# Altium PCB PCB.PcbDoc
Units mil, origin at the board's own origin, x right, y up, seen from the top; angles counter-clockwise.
Board outline 4220 x 3450 mil, 2 copper layers (Top Layer, Bottom Layer), stack 62 mil thick; 138 components, 79 nets, 263 pads, 7 vias.
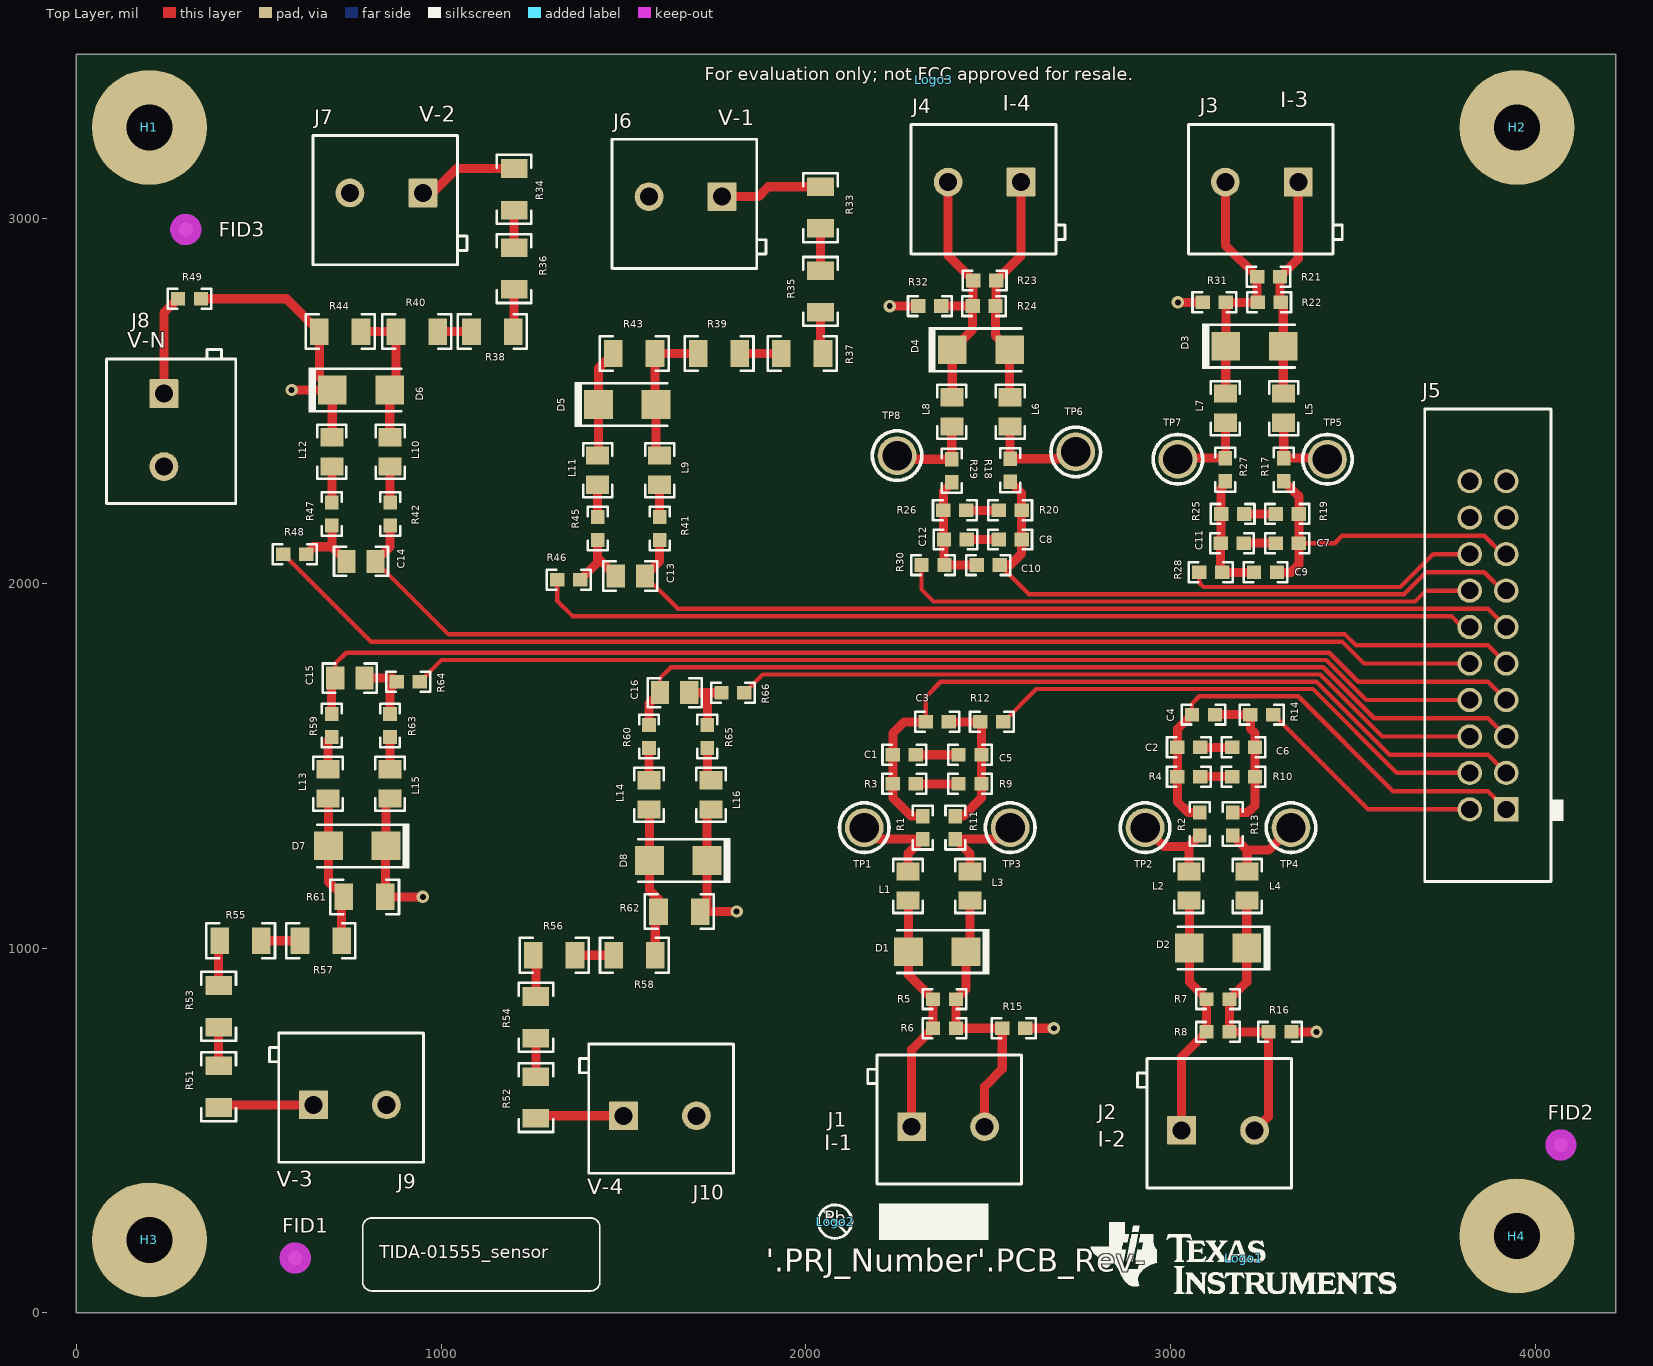
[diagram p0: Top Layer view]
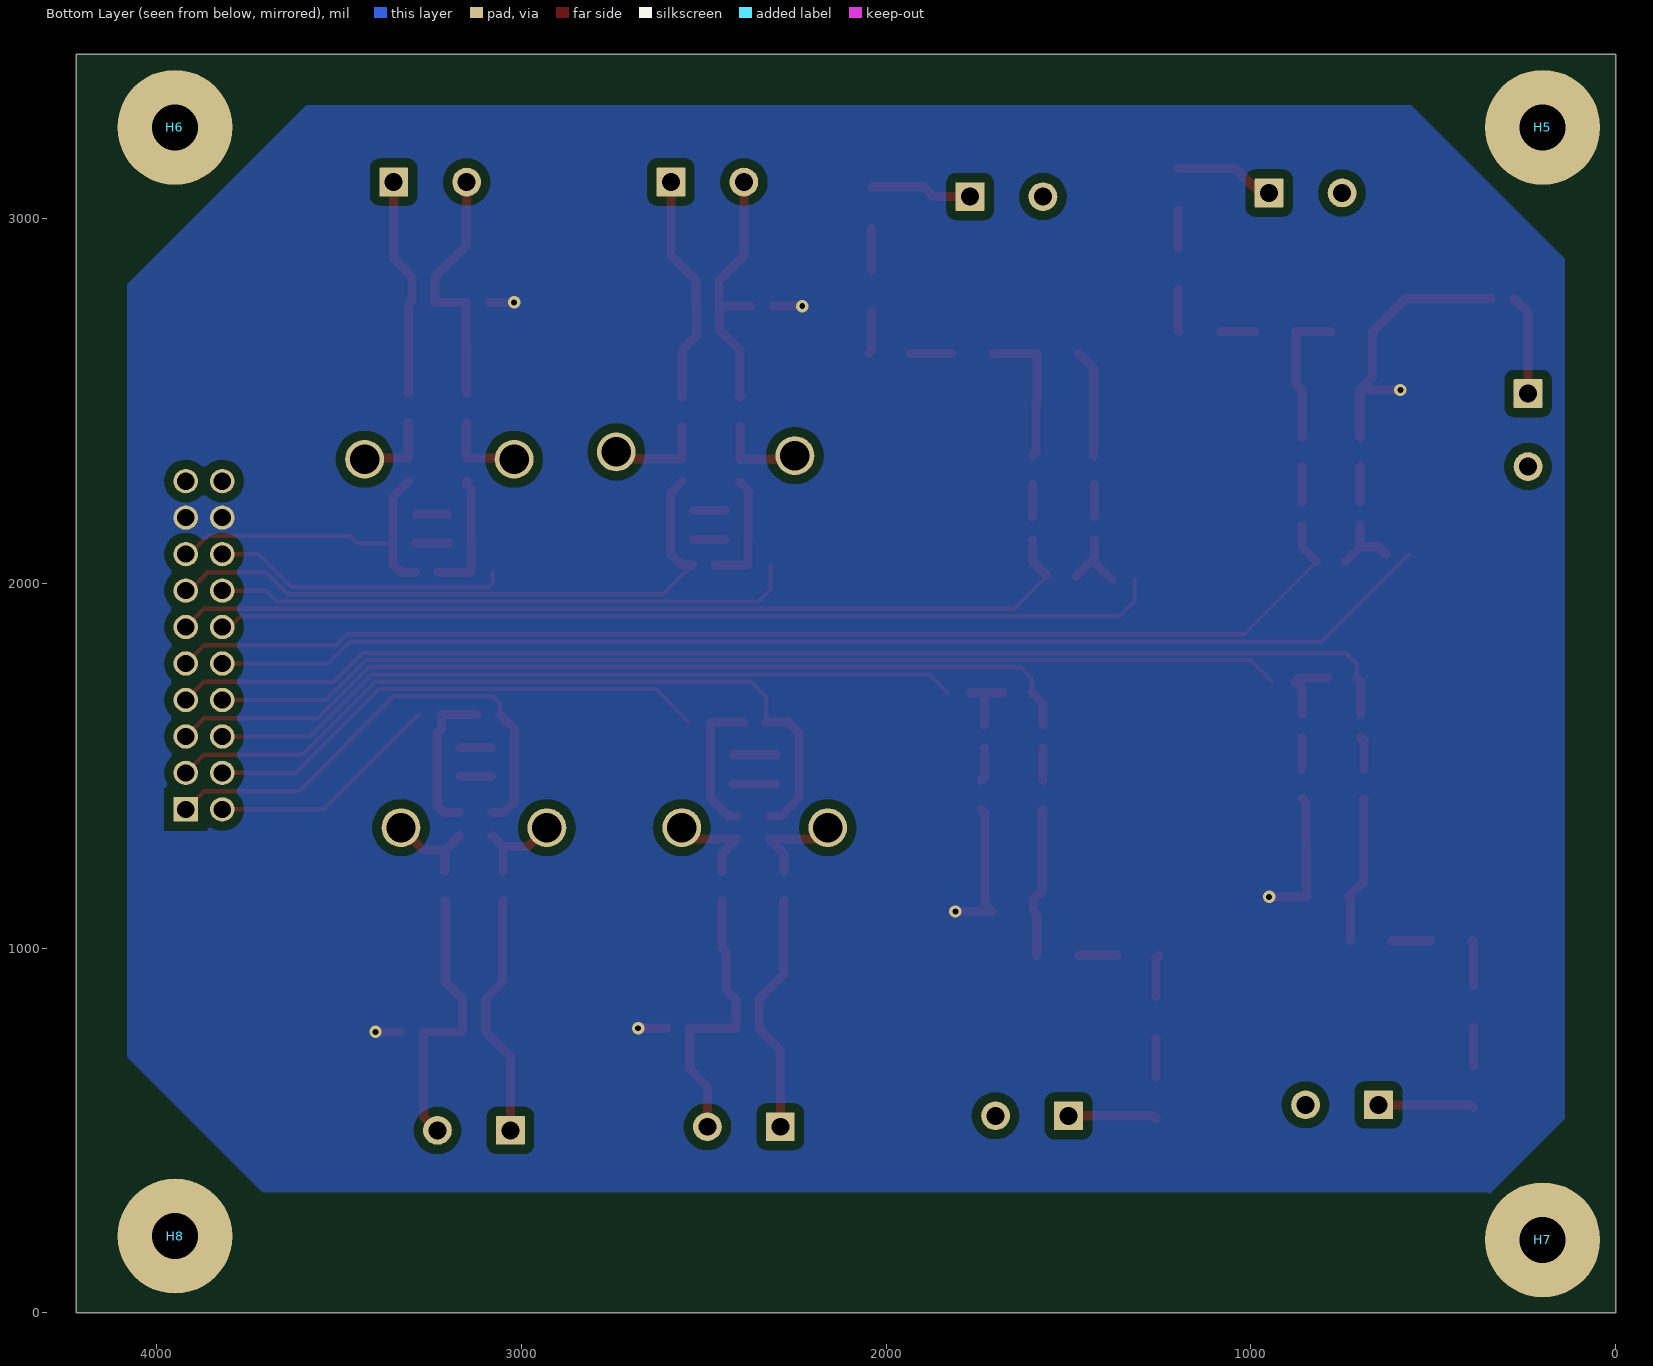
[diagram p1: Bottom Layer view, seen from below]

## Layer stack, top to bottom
Top Solder: solder mask 0.4, Solder Resist, Dk 3.5
Top Layer: signal copper 1.4
Dielectric1: core 59.2, FR-4, Dk 4.8
Bottom Layer: signal copper 1.4
Bottom Solder: solder mask 0.4, Solder Resist, Dk 3.5

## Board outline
0,0 4220,0 4220,3450 0,3450

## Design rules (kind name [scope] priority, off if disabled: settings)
AcuteAngle [All] p1: minimum=4.50000000000000E+0001 checktracksonly=FALSE
AssemblyTestPointUsage [All] p1: valid=2
BoardOutlineClearance BoardOutlineClearance_MountingHoles [OnCopper and InComponentClass('Mounting Holes')] p1: gap=40 ignorepadtopadclearanceinfootprint=FALSE
BoardOutlineClearance BoardOutlineClearance_Poly [OnCopper and IsPoly] p2: gap=25 ignorepadtopadclearanceinfootprint=FALSE
BoardOutlineClearance [OnCopper and Not InComponentClass('Logo') and not InComponentClass('FiducialMark') and not InRegion(1000,500,4000,800) and not InPoly] p3: gap=75 ignorepadtopadclearanceinfootprint=FALSE
Clearance Clearance_Keepouts [((IsTrack Or IsArc) And Not InPoly) And IsFree and IsKeepOut vs ((IsTrack Or IsArc) And Not InPoly) And IsFree and IsKeepOut] p1: gap=0 ignorepadtopadclearanceinfootprint=FALSE
Clearance Clearance_Poly [InPolygon] p2: gap=25 ignorepadtopadclearanceinfootprint=FALSE except(0: Arc-Hole Track-Hole SMDPad-Hole THPad-Hole Via-Hole Fill-Hole Poly-Hole Region-Hole Text-Hole)
Clearance [All] p3: gap=7.87 ignorepadtopadclearanceinfootprint=FALSE except(0: Arc-Hole Track-Hole SMDPad-Hole THPad-Hole Via-Hole Fill-Hole Poly-Hole Region-Hole Text-Hole)
ComponentClearance ComponentClearance_MountingHoles_FiducialMarks [InComponentClass('Mounting Holes') vs InComponentClass('FiducialMark')] p1: gap=50 collisioncheckmode=3 verticalgap=10 showdistances=FALSE
ComponentClearance ComponentClearance_Shunt [InComponentClass('Header') vs InComponentClass('Shunt')] p2: gap=0 collisioncheckmode=3 verticalgap=0 showdistances=FALSE
ComponentClearance ComponentClearance_Logo [InComponentClass('Logo')] p3: gap=50 collisioncheckmode=3 verticalgap=10 showdistances=FALSE
ComponentClearance ComponentClearance_ScrewToNut [(HasFootprint('NY PMS 440 0025 PH')) vs (HasFootprint('Keystone_1902C'))] p4: gap=5 collisioncheckmode=3 verticalgap=10 showdistances=FALSE
ComponentClearance ComponentClearance_MountingHoles [InComponentClass('Mounting Holes')] p5: gap=250 collisioncheckmode=3 verticalgap=100000 showdistances=FALSE
ComponentClearance ComponentClearance_SmallPassives [HasFootprint('0201*') or HasFootprint('0402*') or HasFootprint('0508') or HasFootprint('0603*') or HasFootprint('0612') or HasFootprint('0805*') or HasFootprint('0815*') or HasFootprint('0830*') or HasFootprint('1206*') or HasFootprint('1210*') or HasFootprint('1808*') or HasFootprint('1812*') or HasFootprint('1825*') or HasFootprint('2010*') or HasFootprint('2220*') or HasFootprint('2225*') or HasFootprint('2512*') or HasFootprint('2728*') or HasFootprint('3518*') vs HasFootprint('0201*') or HasFootprint('0402*') or HasFootprint('0508') or HasFootprint('0603*') or HasFootprint('0612') or HasFootprint('0805*') or HasFootprint('0815*') or HasFootprint('0830*') or HasFootprint('1206*') or HasFootprint('1210*') or HasFootprint('1808*') or HasFootprint('1812*') or HasFootprint('1825*') or HasFootprint('2010*') or HasFootprint('2220*') or HasFootprint('2225*') or HasFootprint('2512*') or HasFootprint('2728*') or HasFootprint('3518*')] p6: gap=14.96 collisioncheckmode=3 verticalgap=10 showdistances=FALSE
ComponentClearance ComponentClearance_THtoSMT [IsThruComponent vs IsSMTComponent] p7: gap=40 collisioncheckmode=3 verticalgap=30 showdistances=FALSE
ComponentClearance ComponentClearance_THtoTH [IsThruComponent vs IsThruComponent] p8: gap=30 collisioncheckmode=3 verticalgap=30 showdistances=FALSE
ComponentClearance [All] p9: gap=30 collisioncheckmode=3 verticalgap=10 showdistances=FALSE
DiffPairsRouting [All] p1: maxlimit=100 minlimit=10 mostfreqgap=10 toplayer_minwidth=15 toplayer_maxwidth=15 toplayer_prefwidth=15 bottomlayer_minwidth=15 bottomlayer_maxwidth=15 bottomlayer_prefwidth=15 maxuncoupledlength=1000
FabricationTestPointUsage TestPointUsage [All] p1: valid=2 allowmultiple=FALSE
FabricationTestpoint Testpoint [All] p1: side=3 testpointundercomponent=TRUE minsize=40 maxsize=100 preferedsize=60 minholesize=0 maxholesize=40 preferedholesize=32 testpointgrid=1 allowsidetop=TRUE allowsidebottom=TRUE usegrid=TRUE gridtolerance=0.01
FanoutControl Fanout_LCC [IsLCC] p1: bgadir=Out bgaviamode=Centered fanoutstyle=Auto fanoutdirection=Alternating viagrid=1 // Fanout_LCC (Default Rule)
FanoutControl Fanout_BGA [IsBGA] p2: bgadir=Out bgaviamode=Centered fanoutstyle=Auto fanoutdirection=Alternating viagrid=1 // Fanout_BGA (Default Rule)
FanoutControl Fanout_Default [All] p4: bgadir=Out bgaviamode=Centered fanoutstyle=Auto fanoutdirection=Alternating viagrid=1 // Fanout_Default (Default Rule)
FanoutControl Fanout_Small [(CompPinCount < 5)] p5: bgadir=Out bgaviamode=Centered fanoutstyle=Auto fanoutdirection=OutThenIn viagrid=1 // Fanout_Small (Default Rule)
HoleSize [All] p1: absolutevalues=TRUE maxlimit=251 minlimit=7.87 maxpercent=80.000 minpercent=20.000
MinimumAnnularRing MinimumAnnularRing_ThermalPadVias [IsVia and InAnyComponent] p1: minimumring=5.91
MinimumAnnularRing [All] p2: minimumring=8
MinimumSolderMaskSliver MinimumSolderMaskSliver_Logo [InComponentClass('Logo') vs InComponentClass('Logo')] p1: minsoldermaskwidth=0.7
MinimumSolderMaskSliver [All] p2: minsoldermaskwidth=3.94
PlaneConnect [All] p1: planeconnectstyle=Relief reliefexpansion=10 reliefentries=4 reliefconductorwidth=10 reliefairgap=10
PolygonConnect [All] p1: connectstyle=Direct reliefconductorwidth=10 reliefentries=4 polygonreliefangle="90 Angle" airgapwidth=10
RoutingVias ThermalPadVias [IsVia and InAnyComponent] p1: holewidth=7.87 width=19.68 viastyle="Through Hole" minholewidth=7.87 minwidth=19.68 maxholewidth=12.99 maxwidth=23.62
RoutingVias [All] p2: holewidth=16 width=34 viastyle="Through Hole" minholewidth=7.87 minwidth=26 maxholewidth=40 maxwidth=65
SilkToBoardRegionClearance [Not ((IsComment or IsDesignator) And (Hide <> 'False')) and not InRegion(1000,500,4000,800)] p1:
SilkToSilkClearance SilkToSilkClearance_Pb-FreeLogo [(HasFootprint('Pb-Free_Overlay_Medium') OR HasFootprint('Pb-Free_Overlay_Small')) vs (HasFootprint('Pb-Free_Overlay_Medium') OR HasFootprint('Pb-Free_Overlay_Small'))] p1: silktosilkclearance=0
SilkToSilkClearance [All] p2: silktosilkclearance=4
SilkToSolderMaskClearance SilkToComponentPadClearance [(IsPad or IsFill or IsRegion) and InAnycomponent] p1: minsilkscreentomaskgap=5 clearancetoexposedcopper=TRUE
SilkToSolderMaskClearance "Silk to Solder Mask Opening" [All] p2: minsilkscreentomaskgap=4 clearancetoexposedcopper=FALSE
SolderMaskExpansion [All] p1: expansion=1.97
Width [All] p1: maxlimit=100 minlimit=6 preferedwidth=10 checkconnectedcopper=TRUE
15 further rules are at their usual default settings.

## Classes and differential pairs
component class PT: C13 C14 C15 C16 D5 D6 D7 D8 J6 J7 J8 J9 J10 L9 L10 L11 L12 L13 L14 L15 L16 R33 R34 R35 R36 R37 R38 R39 R40 R41 R42 R43 R44 R45 R46 R47 R48 R49 R51 R52 R53 R54 R55 R56 R57 R58 R59 R60 R61 R62 R63 R64 R65 R66
component class CT: C1 C2 C3 C4 C5 C6 C7 C8 C9 C10 C11 C12 D1 D2 D3 D4 J1 J2 J3 J4 J5 L1 L2 L3 L4 L5 L6 L7 L8 R1 R2 R3 R4 R5 R6 R7 R8 R9 R10 R11 R12 R13 R14 R15 R16 R17 R18 R19 R20 R21 R22 R23 R24 R25 R26 R27 R28 R29 R30 R31 R32 TP1 TP2 TP3 TP4 TP5 TP6 TP7 TP8
component class "Mounting Holes": H1 H2 H3 H4
component class Logo: Logo1
component class EVM_Hardware: FID1 FID2 FID3 H1 H2 H3 H4 H5 H6 H7 H8 Logo1 Logo2 Logo3 TIDA-01555_sensor
component class FiducialMark: FID1 FID2 FID3
component class Label: TIDA-01555_sensor

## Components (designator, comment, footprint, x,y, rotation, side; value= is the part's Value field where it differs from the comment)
C1 "C0603X102K5RACTU" 0603 2270,1530 r0 top value=1000pF
C2 "C0603X102K5RACTU" 0603 3050,1550 r0 top value=1000pF
C3 "06031C103JAT2A" 0603 2360,1620 r0 top value=0.01uF
C4 "06031C103JAT2A" 0603 3090,1640 r0 top value=0.01uF
C5 "C0603X102K5RACTU" 0603 2450,1530 r0 top value=1000pF
C6 "C0603X102K5RACTU" 0603 3200,1550 r0 top value=1000pF
C7 "C0603X102K5RACTU" 0603 3320,2110 r180 top value=1000pF
C8 "C0603X102K5RACTU" 0603 2560,2120 r180 top value=1000pF
C9 "06031C103JAT2A" 0603 3260,2030 r180 top value=0.01uF
C10 "06031C103JAT2A" 0603 2500,2050 r180 top value=0.01uF
C11 "C0603X102K5RACTU" 0603 3168.5,2110 r180 top value=1000pF
C12 "C0603X102K5RACTU" 0603 2410,2120 r180 top value=1000pF
C13 "08055A331KAT2A" 0805_HV 1519.06,2020 r180 top value=330pF
C14 "08055A331KAT2A" 0805_HV 780.32,2060 r180 top value=330pF
C15 "08055A331KAT2A" 0805_HV 749.92,1740 r0 top value=330pF
C16 "08055A331KAT2A" 0805_HV 1640,1700 r0 top value=330pF
D1 "SMAJ12CA" SMA 2360,990 r180 top value=12V
D2 "SMAJ12CA" SMA 3130,1000 r180 top value=12V
D3 "SMAJ12CA" SMA 3230,2650 r0 top value=12V
D4 "SMAJ12CA" SMA 2480,2640 r0 top value=12V
D5 "SMAJ12CA" SMA 1510.31,2490 r0 top value=12V
D6 "SMAJ12CA" SMA 780.31,2530 r0 top value=12V
D7 "SMAJ12CA" SMA 769.92,1280 r180 top value=12V
D8 "SMAJ12CA" SMA 1650,1240 r180 top value=12V
FID1 "Fiducial" Fiducial10-20 600,150 r0 top
FID2 "Fiducial" Fiducial10-20 4070,460 r0 top
FID3 "Fiducial" Fiducial10-20 300,2970 r0 top
H1 "NY PMS 440 0025 PH" "NY PMS 440 0025 PH" 200,3250 r0 top locked
H2 "NY PMS 440 0025 PH" "NY PMS 440 0025 PH" 3950,3250 r0 top locked
H3 "NY PMS 440 0025 PH" "NY PMS 440 0025 PH" 200,200 r0 top locked
H4 "NY PMS 440 0025 PH" "NY PMS 440 0025 PH" 3949.47,210 r0 top locked
H5 "1902C" Keystone_1902C 200,3250 r180 bottom locked
H6 "1902C" Keystone_1902C 3950,3250 r180 bottom locked
H7 "1902C" Keystone_1902C 200,200 r180 bottom locked
H8 "1902C" Keystone_1902C 3949.47,210 r180 bottom locked
J1 "ED120/2DS" On-Shore_ED120_2DS 2390,510 r0 top
J2 "ED120/2DS" On-Shore_ED120_2DS 3130,500 r0 top
J3 "ED120/2DS" On-Shore_ED120_2DS 3250,3100 r180 top
J4 "ED120/2DS" On-Shore_ED120_2DS 2490,3100 r180 top
J5 "SBH11-PBPC-D10-ST-BK" Sullins_SBH11-xxxC-D10-ST 3870,1830 r180 top
J6 "ED120/2DS" On-Shore_ED120_2DS 1670,3060 r180 top
J7 "ED120/2DS" On-Shore_ED120_2DS 850,3070 r180 top
J8 "ED120/2DS" On-Shore_ED120_2DS 240,2420 r270 top
J9 "ED120/2DS" On-Shore_ED120_2DS 750,570 r0 top
J10 "ED120/2DS" On-Shore_ED120_2DS 1600,540 r0 top
L1 "FBMJ2125HM210NT" 0805_HV 2280,1170 r90 top value="21 ohm"
L2 "FBMJ2125HM210NT" 0805_HV 3050,1170 r90 top value="21 ohm"
L3 "FBMJ2125HM210NT" 0805_HV 2450,1170 r90 top value="21 ohm"
L4 "FBMJ2125HM210NT" 0805_HV 3210,1170 r90 top value="21 ohm"
L5 "FBMJ2125HM210NT" 0805_HV 3310,2480 r270 top value="21 ohm"
L6 "FBMJ2125HM210NT" 0805_HV 2560,2470 r270 top value="21 ohm"
L7 "FBMJ2125HM210NT" 0805_HV 3150,2480 r270 top value="21 ohm"
L8 "FBMJ2125HM210NT" 0805_HV 2400,2470 r270 top value="21 ohm"
L9 "FBMJ2125HM210NT" 0805_HV 1599.06,2310 r270 top value="21 ohm"
L10 "FBMJ2125HM210NT" 0805_HV 860.31,2360 r270 top value="21 ohm"
L11 "FBMJ2125HM210NT" 0805_HV 1429.06,2310 r270 top value="21 ohm"
L12 "FBMJ2125HM210NT" 0805_HV 700.31,2360 r270 top value="21 ohm"
L13 "FBMJ2125HM210NT" 0805_HV 689.92,1450 r90 top value="21 ohm"
L14 "FBMJ2125HM210NT" 0805_HV 1570,1420 r90 top value="21 ohm"
L15 "FBMJ2125HM210NT" 0805_HV 859.92,1450 r90 top value="21 ohm"
L16 "FBMJ2125HM210NT" 0805_HV 1740,1420 r90 top value="21 ohm"
Logo1 "Texas Instruments" TI_Stacked_Overlay_Small 3200,150 r0 top
Logo2 "Pb-Free Symbol" Pb-Free_Overlay_Small 2080,250 r0 top
Logo3 "FCC disclaimer" FCC_disclaimer 2350,3380 r0 top
R1 "CRCW06031K00JNEA" 0603 2320,1330 r270 top value=1.0k
R2 "CRCW06031K00JNEA" 0603 3080,1340 r270 top value=1.0k
R3 "RC0603FR-07100KL" 0603 2270,1450 r180 top value=100k
R4 "RC0603FR-07100KL" 0603 3050,1470 r180 top value=100k
R5 "CRCW0603200RFKEA" 0603 2380,860 r180 top value=200
R6 "CRCW0603200RFKEA" 0603 2380,780 r180 top value=200
R7 "CRCW0603200RFKEA" 0603 3130,860 r180 top value=200
R8 "CRCW0603200RFKEA" 0603 3130,770 r180 top value=200
R9 "RC0603FR-07100KL" 0603 2450,1450 r180 top value=100k
R10 "RC0603FR-07100KL" 0603 3200,1470 r180 top value=100k
R11 "CRCW06031K00JNEA" 0603 2410,1330 r270 top value=1.0k
R12 "CRCW06030000Z0EA" 0603 2510,1620 r0 top value=0
R13 "CRCW06031K00JNEA" 0603 3170,1340 r270 top value=1.0k
R14 "CRCW06030000Z0EA" 0603 3250,1640 r0 top value=0
R15 "CRCW06030000Z0EA" 0603 2570,780 r180 top value=0
R16 "CRCW06030000Z0EA" 0603 3300,770 r180 top value=0
R17 "CRCW06031K00JNEA" 0603 3310,2311.5 r90 top value=1.0k
R18 "CRCW06031K00JNEA" 0603 2560,2310 r90 top value=1.0k
R19 "RC0603FR-07100KL" 0603 3320,2190 r0 top value=100k
R20 "RC0603FR-07100KL" 0603 2560,2200 r0 top value=100k
R21 "CRCW0603200RFKEA" 0603 3268.5,2840 r0 top value=200
R22 "CRCW0603200RFKEA" 0603 3270,2770 r0 top value=200
R23 "CRCW0603200RFKEA" 0603 2490,2830 r0 top value=200
R24 "CRCW0603200RFKEA" 0603 2488.5,2760 r0 top value=200
R25 "RC0603FR-07100KL" 0603 3170,2190 r0 top value=100k
R26 "RC0603FR-07100KL" 0603 2408.5,2200 r0 top value=100k
R27 "CRCW06031K00JNEA" 0603 3150,2311.5 r90 top value=1.0k
R28 "CRCW06030000Z0EA" 0603 3110,2030 r180 top value=0
R29 "CRCW06031K00JNEA" 0603 2400,2308.5 r90 top value=1.0k
R30 "CRCW06030000Z0EA" 0603 2348.5,2050 r180 top value=0
R31 "CRCW06030000Z0EA" 0603 3120,2770 r0 top value=0
R32 "CRCW06030000Z0EA" 0603 2340,2760 r0 top value=0
R33 "RC1206FR-07330KL" 1206 2040,3030 r90 top value=330k
R34 "RC1206FR-07330KL" 1206 1200,3080 r90 top value=330k
R35 "RC1206FR-07330KL" 1206 2040,2800 r90 top value=330k
R36 "RC1206FR-07330KL" 1206 1200,2862.91 r90 top value=330k
R37 "RC1206FR-07330KL" 1206 1990,2630 r0 top value=330k
R38 "RC1206FR-07330KL" 1206 1140.31,2690 r0 top value=330k
R39 "RC1206FR-07330KL" 1206 1761.97,2630 r0 top value=330k
R40 "RC1206FR-07330KL" 1206 933.23,2690 r0 top value=330k
R41 "RC0603FR-0712RL" 0603 1599.06,2150 r270 top value=12.0
R42 "RC0603FR-0712RL" 0603 860.31,2190 r270 top value=12.0
R43 "CRCW120629K4FKEA" 1206 1529.06,2630 r180 top value=29.4k
R44 "CRCW120629K4FKEA" 1206 723.23,2690 r180 top value=29.4k
R45 "RC0603FR-0712RL" 0603 1429.06,2150 r270 top value=12.0
R46 "CRCW06030000Z0EA" 0603 1350,2010 r180 top value=0
R47 "RC0603FR-0712RL" 0603 700.31,2190 r270 top value=12.0
R48 "CRCW06030000Z0EA" 0603 598.82,2080 r180 top value=0
R49 "CRCW06030000Z0EA" 0603 310,2780 r180 top value=0
R51 "RC1206FR-07330KL" 1206 390,620 r270 top value=330k
R52 "RC1206FR-07330KL" 1206 1260,590 r270 top value=330k
R53 "RC1206FR-07330KL" 1206 390,840 r270 top value=330k
R54 "RC1206FR-07330KL" 1206 1260,810 r270 top value=330k
R55 "RC1206FR-07330KL" 1206 450,1020 r180 top value=330k
R56 "RC1206FR-07330KL" 1206 1310,980 r180 top value=330k
R57 "RC1206FR-07330KL" 1206 670,1020 r180 top value=330k
R58 "RC1206FR-07330KL" 1206 1530,980 r180 top value=330k
R59 "RC0603FR-0712RL" 0603 699.92,1610 r90 top value=12.0
R60 "RC0603FR-0712RL" 0603 1570,1580 r90 top value=12.0
R61 "CRCW120629K4FKEA" 1206 790,1140 r0 top value=29.4k
R62 "CRCW120629K4FKEA" 1206 1652.91,1100 r0 top value=29.4k
R63 "RC0603FR-0712RL" 0603 859.92,1610 r90 top value=12.0
R64 "CRCW06030000Z0EA" 0603 909.92,1730 r0 top value=0
R65 "RC0603FR-0712RL" 0603 1730,1580 r90 top value=12.0
R66 "CRCW06030000Z0EA" 0603 1800,1700 r0 top value=0
TIDA-01555_sensor "Size: 0.65\" x 0.20 \"" Label_650x200 1110,160 r0 top
TP1 "1573-2" Keystone1573-2 2160,1330 r0 top
TP2 "1573-2" Keystone1573-2 2930,1330 r0 top
TP3 "1573-2" Keystone1573-2 2560,1330 r0 top
TP4 "1573-2" Keystone1573-2 3330,1330 r0 top
TP5 "1573-2" Keystone1573-2 3430,2340 r0 top
TP6 "1573-2" Keystone1573-2 2740,2360 r0 top
TP7 "1573-2" Keystone1573-2 3020,2340 r0 top
TP8 "1573-2" Keystone1573-2 2250,2350 r0 top

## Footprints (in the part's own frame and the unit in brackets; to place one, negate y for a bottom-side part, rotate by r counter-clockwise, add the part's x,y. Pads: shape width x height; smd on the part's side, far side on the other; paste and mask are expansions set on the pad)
0603 [mm] "0603 from SM-752 data"
  rect 1x0.95 smd: 1(-0.8,0) 2(0.8,0)
  silkscreen extent -1.52,-0.69 1.52,0.69, body extent -0.87,-0.47 0.87,0.47, height 1
0805_HV [mil] "0805 with 30mil clearance between pads"
  rect 50x63 smd: 1(-40,0) 2(40,0)
  silkscreen extent -74,-40 74,40, body extent -43,-29 43,29, height 57
1206 [mm] "1206 from SM-752 data"
  rect 1.3x1.85 smd: 1(-1.45,0) 2(1.45,0)
  silkscreen extent -2.4,-1.21 2.4,1.21, body extent -1.7,-0.9 1.7,0.9, height 1.35
FCC_disclaimer [mil]
Fiducial10-20 [mm]
  round 1 smd mask+0.5: 1(0,0)
  Top Layer keep-out circle w1.178: c0,0 r0.5
Keystone1573-2 [mm] "Double Turret"
  round 2.7 hole 2.05: 1(0,0)
  silkscreen extent -1.73,-1.73 1.73,1.73, body extent -1.18,-1.18 1.17,1.18, height 4.72
Keystone_1902C [mil] "Hex Standoff, 4-40 threaded, nylon"
  body extent -145,-126 146,126, height 501
Label_650x200 [mil] "Thermal Transfer Label"
  silkscreen extent -325,-100 325,100, body extent -325,-100 325,100, height 1
"NY PMS 440 0025 PH" [mm] "4-40 nylon screw and mounting hole"
  round 8 hole 3.2: 1(0,0)
  body extent -3.3,-3.3 3.3,3.3, height 2.69
On-Shore_ED120_2DS [mm] "ONSHORE"
  rrect5% 2x2 hole 1.25: 1(-2.54,0)
  round 2 hole 1.25: 2(2.54,0)
  silkscreen extent -5.6,-4 5.12,5, body extent -5.78,-4 5.08,5, height 13
Pb-Free_Overlay_Small [mil]
  silkscreen extent -46,-46 46,46
SMA [mm] "Molded Diode, 2-Leads, Body 4.3x2.6mm, IPC Medium Density, based on OnSemi component dimensions and land pattern"
  rect 2x2 smd: 1(-2,0) 2(2,0)
  silkscreen extent -3.66,-1.57 2.79,1.57, body extent -2.6,-1.3 2.6,1.3, height 2.42
Sullins_SBH11-xxxC-D10-ST [mm] "Header (Shrouded), 2.54mm, 10x2, TH"
  rect 1.7x1.7 hole 1.2: 1(-1.27,11.43)
  round 1.7 hole 1.2: 2(1.27,11.43) 3(-1.27,8.89) 4(1.27,8.89) 5(-1.27,6.35) 6(1.27,6.35) 7(-1.27,3.81) 8(1.27,3.81) 9(-1.27,1.27) 10(1.27,1.27) 11(-1.27,-1.27) 12(1.27,-1.27) 13(-1.27,-3.81) 14(1.27,-3.81) 15(-1.27,-6.35) 16(1.27,-6.35) 17(-1.27,-8.89) 18(1.27,-8.89) 19(-1.27,-11.43) 20(1.27,-11.43)
  silkscreen extent -5.25,-16.45 4.4,16.45, body extent -4.4,-16.45 4.7,16.45, height 9.11
TI_Stacked_Overlay_Small [mil]
  silkscreen extent -418,-98 418,98

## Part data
C1 C2 C5 C6 C7 C8 C11 C12: library part CMP-0006976-5, "CAP, CERM, 1000 pF, 50 V, +/- 10%, X7R, 0603", Cap_Case=0603, Manufacturer=Kemet, Supplier Part Number 1=399-5348-1-ND, TempCo=X7R, Tolerance_%=10%, Value1=Unknown, Value2=50V, ValueDisplayed=1000pF
C3 C4 C9 C10: library part CMP-0006726-4, "CAP, CERM, 0.01 uF, 100 V, +/- 5%, X7R, 0603", Cap_Case=0603, Manufacturer=AVX, Supplier Part Number 1=478-3700-1-ND, TempCo=X7R, Tolerance_%=5%, Value1="0.098 ohm", Value2=100V, ValueDisplayed=0.01uF
C13 C14 C15 C16: library part CMP-0007609-2, "CAP, CERM, 330 pF, 50 V, +/- 10%, C0G/NP0, 0805", Cap_Case=0805, Manufacturer=AVX, Supplier Part Number 1=478-3765-1-ND, TempCo=C0G/NP0, Tolerance_%=10%, Value1="0.189 ohm", Value2=50V, ValueDisplayed=330pF
D1 D2 D3 D4 D5 D6 D7 D8: library part CMP-0005430-2, "Diode, TVS, Bi, 12 V, SMA", Manufacturer=Littelfuse, Power_W=3.3W, Supplier Part Number 1=SMAJ12CALFCT-ND
FID1 FID2 FID3: "Fiducial mark.  There is nothing to buy or mount.", Manufacturer=N/A
H1 H2 H3 H4: "Machine Screw, Round, #4-40 x 1/4, Nylon, Philips panhead", DigiKeyPartNumber=H542-ND, Manufacturer="B&F Fastener Supply"
H5 H6 H7 H8: "Standoff, Hex, 0.5\"L #4-40 Nylon", Alternate Manufacturer=-, Manufacturer=Keystone, Supplier Part Number 1=1902CK-ND
J1 J2 J3 J4 J6 J7 J8 J9 J10: library part CMP-0074910-1, "Terminal Block, 5.08 mm, 2x1, Brass, TH", Color=Blue, Current_A=15A, Manufacturer="On-Shore Technology", Supplier Part Number 1=ED1609-ND, Voltage_V=300V
J5: "Header (Shrouded), 2.54mm, 10x2, Gold, Black, TH", Color=Black, Current_A=3, Manufacturer="Sullins Connector Solutions", Supplier Part Number 1=S9172-ND, Voltage_V=1000
L1 L2 L3 L4 L5 L6 L7 L8 L9 L10 L11 L12 L13 L14 L15 L16: library part CMP-0003375-1, "Ferrite Bead, 21 ohm @ 100 MHz, 6 A, 0805", Manufacturer="Taiyo Yuden", Supplier Part Number 1=587-1765-1-ND, Value1="0.004 ohm", Value2=6A, ValueDisplayed="21 ohm"
Logo1: library part TI_Logo, "Texas Instrument Corporate Signature"
Logo2: library part Pb-Free
Logo3: library part FCC_disclaimer, "FCC_disclaimer"
R1 R2 R11 R13 R17 R18 R27 R29: "RES, 1.0 k, 5%, 0.1 W, 0603", Manufacturer=Vishay-Dale, Power_W=0.1, Supplier Part Number 1=541-1.0KGCT-ND, TempCo="200 ppm/C", Tolerance_%=5, Value1=5%, Value2=0.1W, Value_Code=1k00, ValueDisplayed=1.0k
R3 R4 R9 R10 R19 R20 R25 R26: library part CMP-0022735-3, "RES, 100 k, 1%, 0.1 W, 0603", Manufacturer="Yageo America", Power_W=100mW, Supplier Part Number 1=311-100KHRCT-ND, TempCo="200 ppm/C", Tolerance_%=1%, Value2=0.1W, Value_Code=100k
R5 R6 R7 R8 R21 R22 R23 R24: "RES, 200, 1%, 0.1 W, 0603", Manufacturer=Vishay-Dale, Power_W=0.1, Supplier Part Number 1=541-200HCT-ND, TempCo="100 ppm/C", Tolerance_%=1, Value1=1%, Value2=0.1W, Value_Code=200R, ValueDisplayed=200
R12 R14 R15 R16 R28 R30 R31 R32 R46 R48 R49 R64 R66: library part CMP-0025697-3, "RES, 0, 5%, 0.1 W, 0603", Manufacturer=Vishay-Dale, Power_W=100mW, Supplier Part Number 1=541-0.0GCT-ND, TempCo="200 ppm/C", Tolerance_%=5%, Value2=0.1W, Value_Code=0000, ValueDisplayed=0
R33 R34 R35 R36 R37 R38 R39 R40 R51 R52 R53 R54 R55 R56 R57 R58: library part CMP-0018205-2, "RES, 330 k, 1%, 0.25 W, 1206", Manufacturer="Yageo America", Power_W=250mW, Supplier Part Number 1=311-330KFRCT-ND, TempCo="100 ppm/C", Tolerance_%=1%, Value2=0.25W, Value_Code=330k
R41 R42 R45 R47 R59 R60 R63 R65: library part CMP-0022783-2, "RES, 12.0, 1%, 0.1 W, 0603", Manufacturer="Yageo America", Power_W=100mW, Supplier Part Number 1=311-12.0HRCT-ND, TempCo="200 ppm/C", Tolerance_%=1%, Value2=0.1W, Value_Code=12R0, ValueDisplayed=12.0
R43 R44 R61 R62: library part CMP-0016842-2, "RES, 29.4 k, 1%, 0.25 W, 1206", Manufacturer=Vishay-Dale, Power_W=250mW, Supplier Part Number 1=541-29.4KFCT-ND, TempCo="100 ppm/C", Tolerance_%=1%, Value2=0.25W, Value_Code=29k4, ValueDisplayed=29.4k
TIDA-01555_sensor: library part THT-14-423-10, "Thermal Transfer Printable Labels, 0.650\" W x 0.200\" H - 10,000 per roll", Alternate Manufacturer=-, Manufacturer=Brady, Supplier Part Number 1=2065596
TP1 TP2 TP3 TP4 TP5 TP6 TP7 TP8: library part CMP-0055119-1, "Terminal, Turret, TH, Double", Manufacturer=Keystone, Supplier Part Number 1=36-1573-2-ND

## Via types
v1: diameter 34, hole 16, Top Layer to Bottom Layer, 7 vias

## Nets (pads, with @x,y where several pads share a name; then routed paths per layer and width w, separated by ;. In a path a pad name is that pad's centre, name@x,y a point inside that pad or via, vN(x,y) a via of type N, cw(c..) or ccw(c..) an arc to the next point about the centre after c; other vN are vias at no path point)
A0+: C13.1 J5.11 R41.2 | length 2534
  Top Layer w12: C13.1 1649.05,1930 3870,1930 J5.11
  Top Layer w25: C13.1 1599.06,2060 R41.2
A0-: J5.12 R46.2 | length 2589.6
  Top Layer w12: R46.2 1318.5,1951.5 1360,1910 3770,1910 3790,1890 3810,1890 J5.12
A1+: C14.1 J5.9 R42.2 | length 3330.7
  Top Layer w12: C14.1 1020.44,1859.87 3478.23,1859.87 3508.11,1830 3870,1830 J5.9
  Top Layer w25: C14.1 860.31,2100 R42.2
A1-: J5.10 R48.2 | length 3376.9
  Top Layer w12: R48.2 807.32,1840 3470,1840 3530,1780 J5.10
A2+: C15.1 J5.7 R59.2 | length 3418.6
  Top Layer w12: C15.1 709.92,1779.92 739.62,1809.62 3434.7,1809.62 3514.32,1730 3870,1730 J5.7
  Top Layer w25: R59.2 699.92,1730 C15.1
A2-: J5.8 R64.2 | length 2948.8
  Top Layer w12: R64.2 1001.17,1789.75 3426.46,1789.75 3536.21,1680 J5.8
A3+: C16.1 J5.5 R60.2 | length 2552
  Top Layer w12: C16.1 1600,1740 1629.87,1769.87 3418.23,1769.87 3558.11,1630 3870,1630 J5.5
  Top Layer w25: R60.2 1570,1670 C16.1
A3-: J5.6 R66.2 | length 2079.6
  Top Layer w12: R66.2 1881.5,1750 3410,1750 3580,1580 J5.6
A4+: C1.1 C3.1 J5.3 R1.1 R3.2 | length 2163
  Top Layer w12: C3.1 2328.5,1688.5 2370,1730 3400,1730 3600,1530 3870,1530 J5.3
  Top Layer w25: R1.1 2288.5,1361.5 2238.5,1411.5 R3.2 C1.1 2238.5,1588.5 2270,1620 C3.1
A4-: J5.4 R12.2 | length 1411.1
  Top Layer w12: R12.2 2631.5,1710 3390,1710 3620,1480 J5.4
A5+: C2.1 C4.1 J5.1 R2.1 R4.2 | length 1357
  Top Layer w12: C4.1 3058.5,1669.77 3078.73,1690 3350,1690 3610,1430 3870,1430 J5.1
  Top Layer w25: C4.1 3018.5,1600 C2.1 R4.2 3018.5,1401.5 3048.5,1371.5 R2.1
A5-: J5.2 R14.2 | length 646.2
  Top Layer w12: R14.2 3541.5,1380 J5.2
A6+: C7.1 C9.1 J5.15 R17.1 R19.2 | length 912.1
  Top Layer w12: C7.1 3450,2110 3470,2130 3860,2130 3910,2080 J5.15
  Top Layer w25: C9.1 3330,2030 3351.5,2051.5 C7.1 R19.2 3351.5,2238.5 R17.1
A6-: J5.16 R28.2 | length 812.1
  Top Layer w12: R28.2 3078.5,2001.5 3090.13,1989.87 3629.87,1989.87 3720,2080 J5.16
A7+: C8.1 C10.1 J5.13 R18.1 R20.2 | length 1750.3
  Top Layer w12: C10.1 2611.5,1970 3640,1970 3700,2030 3860,2030 3910,1980 J5.13
  Top Layer w25: C10.1 2560,2050 2591.5,2081.5 C8.1 R20.2 2591.5,2247.01 R18.1
A7-: J5.14 R30.2 | length 1596.2
  Top Layer w12: R30.2 2317.01,1982.99 2350.13,1949.87 3669.87,1949.87 3700,1980 J5.14
AGND: D6.1 D7.1 D8.1 J5.17 J5.18 L12.1 L15.1 L16.1 R15.1 R16.1 R31.1 R32.1 R44.2 R49.1 R61.2 R62.2 | length 1843.4
  Top Layer w25: R49.1 576.14,2780 R44.2 666.14,2565.43 D6.1 ; v1(590,2530) D6.1 ; L12.1 701.57,2401.26 D6.1 ; L15.1 848.66,1398.74 D7.1 847.09,1278.43 R61.2 v1(950,1140) ; L16.1 1728.74,1368.74 D8.1 1728.74,1118.74 R62.2 v1(1810,1100) ; v1(2230,2760) R32.1 ; R15.1 v1(2680,780) ; v1(3020,2770) R31.1 ; R16.1 v1(3400,770)
NetC1_2: C1.2 C5.1 | length 117
  Top Layer w25: C1.2 C5.1
NetC2_2: C2.2 C6.1 | length 87
  Top Layer w25: C2.2 C6.1
NetC3_2: C3.2 C5.2 R9.1 R11.1 R12.1 | length 389
  Top Layer w25: C3.2 R12.1 2481.5,1617.01 C5.2 R9.1 2481.5,1411.5 2431.5,1361.5 R11.1
NetC4_2: C4.2 C6.2 R10.1 R13.1 R14.1 | length 420.7
  Top Layer w25: C4.2 R14.1 3218.5,1601.5 3231.5,1588.5 C6.2 R10.1 3231.5,1391.5 3211.5,1371.5 R13.1
NetC7_2: C7.2 C11.1 | length 88.5
  Top Layer w25: C11.1 C7.2
NetC8_2: C8.2 C12.1 | length 87
  Top Layer w25: C12.1 C8.2
NetC9_2: C9.2 C11.2 R25.1 R27.1 R28.1 | length 344.2
  Top Layer w25: R27.1 3150,2271.51 3138.5,2260.02 R25.1 3138.5,2111.5 C11.2 3137.01,2034.49 R28.1 C9.2
NetC10_2: C10.2 C12.2 R26.1 R29.1 R30.1 | length 326.3
  Top Layer w25: R29.1 2400,2275.79 2377.01,2252.8 R26.1 2377.01,2121.5 C12.2 2378.5,2051.5 R30.1 C10.2
NetC13_2: C13.2 R45.2 R46.1 | length 198.9
  Top Layer w25: R46.1 1429.06,2057.56 1429.06,2070 ; R45.2 1429.06,2070 ; C13.2 1429.06,2070
NetC14_2: C14.2 R47.2 R48.1 | length 193.4
  Top Layer w25: R48.1 650.31,2100 700.31,2100 ; R47.2 700.31,2100 ; C14.2 700.31,2100
NetC15_2: C15.2 R63.2 R64.1 | length 188.8
  Top Layer w25: C15.2 868.43,1740 R64.1 859.92,1711.5 R63.2
NetC16_2: C16.2 R65.2 R66.1 | length 177
  Top Layer w25: C16.2 1730,1700 ; R65.2 1730,1700 ; R66.1 1730,1700
NetD1_1: D1.1 J1.2 L3.1 R5.1 R6.1 R15.2 | length 783
  Top Layer w25: L3.1 2450,1001.26 D1.1 2438.74,887.24 R5.1 R6.1 R15.2 2538.5,668.5 2490,620 J1.2
NetD1_2: D1.2 J1.1 L1.1 R5.2 R6.2 | length 673.7
  Top Layer w25: L1.1 2281.26,1128.74 D1.2 2281.26,929.76 2280,928.5 R5.2 R6.2 2290,721.5 J1.1
NetD2_1: D2.1 J2.2 L4.1 R7.1 R8.1 R16.2 | length 773
  Top Layer w25: L4.1 3208.74,1128.74 D2.1 3208.74,907.24 R7.1 R8.1 R16.2 3268.5,538.5 J2.2
NetD2_2: D2.2 J2.1 L2.1 R7.2 R8.2 | length 678.5
  Top Layer w25: J2.1 3030,701.5 R8.2 R7.2 3051.26,907.24 D2.2 3051.26,1128.74 L2.1
NetD3_1: D3.1 J3.2 L7.1 R21.1 R22.1 R31.2 | length 704.3
  Top Layer w25: L7.1 3151.26,2521.26 D3.1 3151.5,2650.24 R31.2 R22.1 3237.01,2771.5 R21.1 3150,2927.01 J3.2
NetD3_2: D3.2 J3.1 L5.1 R21.2 R22.2 | length 604.9
  Top Layer w25: L5.1 3308.74,2521.26 D3.2 3308.74,2762.76 R22.2 3300,2771.5 R21.2 3350,2890 J3.1
NetD4_1: D4.1 J4.2 L8.1 R23.1 R24.1 R32.2 | length 728.1
  Top Layer w25: R32.2 R24.1 ; J4.2 2390,2898.5 R23.1 2458.5,2761.5 R24.1 ; L8.1 2401.26,2511.26 D4.1 2457.01,2695.75 R24.1
NetD4_2: D4.2 J4.1 L6.1 R23.2 R24.2 | length 635.6
  Top Layer w25: L6.1 2558.74,2511.26 D4.2 2520,2678.74 R24.2 2521.5,2761.5 R23.2 2590,2898.5 J4.1
NetD5_1: D5.1 L11.1 R43.2 | length 297.8
  Top Layer w25: L11.1 1431.57,2352.52 D5.1 1431.57,2589.61 R43.2
NetD5_2: D5.2 L9.1 R39.1 R43.1 | length 404.1
  Top Layer w25: L9.1 1589.06,2360 D5.2 1586.14,2492.91 R43.1 R39.1
NetD6_2: D6.2 L10.1 R40.1 R44.1 | length 393.4
  Top Layer w25: R44.1 R40.1 876.14,2547.09 D6.2 859.06,2401.26 L10.1
NetD7_2: D7.2 L13.1 R57.1 R61.1 | length 410.2
  Top Layer w25: L13.1 691.18,1408.74 D7.2 691.18,1181.73 R61.1 727.09,1134.17 R57.1
NetD8_2: D8.2 L14.1 R58.1 R62.1 | length 414.3
  Top Layer w25: L14.1 1571.26,1378.74 D8.2 1571.26,1158.74 1595.83,1134.17 R62.1 1587.09,1091.26 R58.1
NetJ6_1: J6.1 R33.2 | length 281.2
  Top Layer w25: J6.1 1870,3060 1897.09,3087.09 R33.2
NetJ7_1: J7.1 R34.2 | length 277.8
  Top Layer w25: J7.1 975.28,3070 1042.36,3137.09 R34.2
NetJ8_1: J8.1 R49.2 | length 275.9
  Top Layer w25: J8.1 240,2741.5 R49.2
NetJ9_1: J9.1 R51.2 | length 262.9
  Top Layer w25: R51.2 397.09,570 J9.1
NetJ10_1: J10.1 R52.2 | length 242.9
  Top Layer w25: R52.2 1267.09,540 J10.1
NetL1_2: L1.2 R1.2 TP1.1 | length 278.1
  Top Layer w25: TP1.1 2191.5,1298.5 R1.2 2280,1258.5 L1.2
NetL2_2: L2.2 R2.2 TP2.1 | length 252.3
  Top Layer w25: TP2.1 2981.5,1278.5 3050,1278.5 ; L2.2 3050,1278.5 ; R2.2 3050,1278.5
NetL3_2: L3.2 R11.2 TP3.1 | length 268.1
  Top Layer w25: L3.2 2450,1258.5 R11.2 2528.5,1298.5 TP3.1
NetL4_2: L4.2 R13.2 TP4.1 | length 260.5
  Top Layer w25: R13.2 3210,1268.5 ; L4.2 3210,1268.5 ; TP4.1 3268.5,1268.5 3210,1268.5
NetL5_2: L5.2 R17.2 TP5.1 | length 218.2
  Top Layer w25: L5.2 R17.2 3427.01,2342.99 TP5.1
NetL6_2: L6.2 R18.2 TP6.1 | length 276.2
  Top Layer w25: L6.2 R18.2 2721.5,2341.5 TP6.1
NetL7_2: L7.2 R27.2 TP7.1 | length 228.2
  Top Layer w25: TP7.1 3022.99,2342.99 R27.2 L7.2
NetL8_2: L8.2 R29.2 TP8.1 | length 244.1
  Top Layer w25: TP8.1 2260,2340 R29.2 L8.2
NetL9_2: L9.2 R41.1 | length 88.5
  Top Layer w25: R41.1 L9.2
NetL10_2: L10.2 R42.1 | length 98.5
  Top Layer w25: R42.1 L10.2
NetL11_2: L11.2 R45.1 | length 88.5
  Top Layer w25: R45.1 L11.2
NetL12_2: L12.2 R47.1 | length 98.5
  Top Layer w25: R47.1 L12.2
NetL13_2: L13.2 R59.1 | length 92.6
  Top Layer w25: L13.2 689.92,1568.5 R59.1
NetL14_2: L14.2 R60.1 | length 88.5
  Top Layer w25: L14.2 R60.1
NetL15_2: L15.2 R63.1 | length 88.5
  Top Layer w25: L15.2 R63.1
NetL16_2: L16.2 R65.1 | length 92.6
  Top Layer w25: R65.1 1730,1470 L16.2
NetR3_1: R3.1 R9.2 | length 117
  Top Layer w25: R3.1 R9.2
NetR4_1: R4.1 R10.2 | length 87
  Top Layer w25: R4.1 R10.2
NetR19_1: R19.1 R25.2 | length 87
  Top Layer w25: R25.2 R19.1
NetR20_1: R20.1 R26.2 | length 88.5
  Top Layer w25: R26.2 R20.1
NetR33_1: R33.1 R35.2 | length 115.8
  Top Layer w25: R35.2 R33.1
NetR34_1: R34.1 R36.2 | length 102.9
  Top Layer w25: R36.2 R34.1
NetR35_1: R35.1 R37.2 | length 115.8
  Top Layer w25: R35.1 2040,2637.09 R37.2
NetR36_1: R36.1 R38.2 | length 116.9
  Top Layer w25: R38.2 1200,2692.6 R36.1
NetR37_1: R37.1 R39.2 | length 113.9
  Top Layer w25: R39.2 R37.1
NetR38_1: R38.1 R40.2 | length 92.9
  Top Layer w25: R40.2 R38.1
NetR51_1: R51.1 R53.2 | length 105.8
  Top Layer w25: R51.1 R53.2
NetR52_1: R52.1 R54.2 | length 105.8
  Top Layer w25: R52.1 R54.2
NetR53_1: R53.1 R55.2 | length 124.1
  Top Layer w25: R53.1 390,1017.09 R55.2
NetR54_1: R54.1 R56.2 | length 115.8
  Top Layer w25: R56.2 1260,972.91 R54.1
NetR55_1: R55.1 R57.2 | length 105.8
  Top Layer w25: R55.1 R57.2
NetR56_1: R56.1 R58.2 | length 105.8
  Top Layer w25: R56.1 R58.2
pads on no net: FID1.1 FID2.1 FID3.1 H1.1 H2.1 H3.1 H4.1 J5.19 J5.20 J6.2 J7.2 J8.2 J9.2 J10.2

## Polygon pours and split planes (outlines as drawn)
AGND on Bottom Layer "BOTTOM_LAYER_AGND_P000" (solid, remove dead copper, pour order 0): 140,2890 140,530 140.93,530 344.95,325.98 348.96,330 3710,330 4080,700 4080,2820 3590,3310 560,3310

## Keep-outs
Keep-Out Layer:
  text ".Layer_Name" at 577,-858.49 h60

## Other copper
Top Layer:
  text ".Layer_Name" at 577,-858.49 h60
Bottom Layer:
  text ".Layer_Name" at 577,-858.49 h60

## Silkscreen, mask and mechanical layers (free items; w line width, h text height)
Top Overlay:
  region: 2500,300 2200,300 2200,200 2500,200
  text "I-3" at 3300,3290 h72.83
  text "I-4" at 2540,3280 h72.83
  text "V-2" at 940,3250 h72.83
  text "V-1" at 1760,3240 h72.83
  text "V-N" at 140,2630 h72.83
  text "I-2" at 2800,440 h72.83
  text "I-1" at 2050,430 h72.83
  text "V-3" at 550,330 h72.83
  text "V-4" at 1400,310 h72.83
  text "'.PRJ_Number'.PCB_Rev-" at 1890,90 h108.27
  text ".Layer_Name" at 577,-858.49 h60
Bottom Overlay:
  text ".Layer_Name" at 577,-858.49 h60
Top Paste:
  text ".Layer_Name" at 577,-858.49 h60
Bottom Paste:
  text ".Layer_Name" at 577,-858.49 h60
Top Solder:
  text ".Layer_Name" at 577,-858.49 h60
  text ".Layer_Name" at 577,-858.49 h60
Bottom Solder:
  text ".Layer_Name" at 577,-858.49 h60
Drill Guide:
  text ".Layer_Name" at 577,-858.49 h60
M1 Board Outline:
  lines w10: 0,0 0,3450 4210,3450 4210,0 0,0
  text ".Layer_Name" at 577,-858.49 h60
M2 Board Dimensions:
  rectangle: 0,-275 125,-150
  rectangle: 125,-400 500,-275
  lines w7: 0,-275 1000,-275 ; 125,-400 125,-150 ; 250,-400 250,-150 ; 500,-400 500,-150 ; 750,-400 750,-150 ; 0,-400 1000,-400 1000,-150 0,-150 0,-400
  text ".Layer_Name" at 577,-858.49 h60
M3 3D STEP Top:
  text ".Layer_Name" at 577,-858.49 h60
M4 3D STEP Bottom:
  text ".Layer_Name" at 577,-858.49 h60
M5 Assembly Top:
  lines w10: -292,-930.17 6308,-930.17 ; -292,-726.83 6310,-726.83 ; -292,-523.5 -292,-1133.5 3713,-1133.5 6310,-1133.5 6310,-523.5 -291.5,-523.5 -291.5,-1133.5 1284,-1133.5 ; 2173,-1133.5 2173,-523.5 ; 3440,-726.83 3440,-523.5 ; 4280,-726.83 4280,-523.5 ; 4902,-1140 4902,-937.17
  text "COMPONENTS MARKED 'DNP' SHOULD NOT BE POPULATED." at 1153.5,-318.5 h60
  text "ASSEMBLY VARIANT:" at 1153,-434 h60
  text ".VariantName" at 2189,-434 h60
  text "PCB VIEWED FROM TOP SIDE" at -228.5,-655.67 h60
  text "BOARD #:" at 2248,-655.67 h60
  text ".PRJ_Number" at 2793.5,-655.67 h60
  text "REV:" at 3638,-655.67 h60
  text ".PCB_Rev" at 3929.5,-655.67 h60
  text "SVN REV:" at 4476,-655.67 h60
  text ".VersionControl_RevNumber" at 4982,-655.67 h60
  text "TID #:" at 2248,-859 h60
  text ".TID" at 2793.5,-859 h60
  text "PLOT NAME =" at -228.5,-1064.34 h60
  text ".plot_File_Name" at 577,-1064.34 h60
  text "GENERATED    :" at 2250,-1064.34 h60
  text ".Print_Date" at 3119.5,-1064.34 h60
  text ".Print_Time" at 3848.5,-1064.34 h60
  text "TEXAS INSTRUMENTS" at 5113,-1064.34 h60
M6 Assembly Bottom:
  lines w10: -292.5,-727.33 6309.5,-727.33 ; -290.5,-930.67 6309.5,-930.67 ; 1115.5,-1140.5 1115.5,-937.67 ; 1737.5,-727.33 1737.5,-524 ; 2577.5,-727.33 2577.5,-524 ; 3844.5,-1134 3844.5,-524 ; 4733.5,-1134 6309,-1134 6309,-524 -292.5,-524 -292.5,-1134 2304.5,-1134 6309.5,-1134 6309.5,-524
  text "COMPONENTS MARKED 'DNP' SHOULD NOT BE POPULATED." at 6102,-318 h60
  text ".VariantName" at 5058,-434 h60
  text "ASSEMBLY VARIANT:" at 6097,-434 h60
  text ".VersionControl_RevNumber" at 1035.5,-656.17 h60
  text "SVN REV:" at 1541.5,-656.17 h60
  text ".PCB_Rev" at 2088,-656.17 h60
  text "REV:" at 2379.5,-656.17 h60
  text ".PRJ_Number" at 3224,-656.17 h60
  text "BOARD #:" at 3769.5,-656.17 h60
  text "PCB VIEWED FROM BOTTOM SIDE" at 6246,-656.17 h60
  text ".TID" at 3224,-859.5 h60
  text "TID #:" at 3769.5,-859.5 h60
  text "TEXAS INSTRUMENTS" at 904.5,-1064.84 h60
  text ".Print_Time" at 2169,-1064.84 h60
  text ".Print_Date" at 2898,-1064.84 h60
  text "GENERATED    :" at 3767.5,-1064.84 h60
  text ".plot_File_Name" at 5440.5,-1064.84 h60
  text "PLOT NAME =" at 6246,-1064.84 h60
M9 Title Sheet:
  drawing of 57 lines, arcs and shapes, not listed
  text "1" at 739.84,8036.5 h70
  text "2" at 3235.5,8036.5 h70
  text "3" at 5724.84,8036.5 h70
  text "4" at 8231.51,8036.5 h70
  text "5" at 10730.5,8036.5 h70
  text "6" at 13235.5,8036.5 h70
  text "A" at -416.5,6893.5 h70
  text "A" at 14383.5,6893.5 h70
  text "B" at -416.5,4513.5 h70
  text "B" at 14383.5,4513.5 h70
  text "C" at -416.5,2138.5 h70
  text "C" at 14383.5,2138.5 h70
  text "PROJECT TITLE:" at 11343.5,277.5 h45
  text ".PRJ_Title" at 11393.5,144.17 h70
  text "DESIGNED FOR:" at 11343.5,-23.5 h45
  text ".PRJ_Customer" at 11393.5,-163.5 h70
  text "D" at -416.5,-231.5 h70
  text "D" at 14383.5,-231.5 h70
  text "FILE NAME:" at 11343.5,-323.5 h45
  text ".PCB_File_Name_No_Path" at 11393.5,-443.5 h70
  text "Texas Instruments (TI) and/or its licensors do not warrant the accuracy or completeness of this specification" at 6374,-605.34 h45
  text "ENGINEER:" at 11343.5,-613.5 h45
  text "LAYOUT BY:" at 12848.5,-613.5 h45
  text "or any information contained therein. TI and/or its licensors do not warrant that this design will meet" at 6329.01,-718 h45
  text ".PRJ_Engineer" at 11393.5,-768.49 h70
  text ".PCB_Layout" at 12899,-768.49 h70
  text "the specifications, will be suitable for your application or fit for any particular purpose, or will operate in" at 6329.01,-830.67 h45
  text ".Layer_Name" at 577,-858.49 h60
  text "ALTIUM DESIGNER VERSION:" at 12848.5,-923.5 h45
  text "an implementation. TI and/or its licensors do not warrant that the design is production worthy. You should" at 6329.01,-943.33 h45
  text "completely validate and test your design implementation to confirm the system functionality for your application." at 6374,-1056 h45
  text ".print_Scale" at 11393.5,-1056.83 h70
  text ".Application_BuildNumber" at 12899,-1056.83 h70
  text "1" at 739.84,-1263.5 h70
  text "2" at 3235.5,-1263.5 h70
  text "3" at 5724.84,-1263.5 h70
  text "4" at 8231.51,-1263.5 h70
  text "5" at 10730.5,-1263.5 h70
  text "6" at 13235.5,-1263.5 h70
M10 Fab Notes:
  drawing of 173 lines, arcs and shapes, not listed
  text "DESIGN INFORMATION" at 12378.02,6201 h60
  text "MIN. TRACK WIDTH:" at 11733.46,6021 h60
  text "8" at 12829.7,6021 h60
  text "MIL" at 12984.46,6021 h60
  text "MIN. CLEARANCE:" at 11733.46,5889 h60
  text "0.2" at 12769.7,5889 h60
  text "mm" at 12984.46,5889 h60
  text "MIN. VIA PAD SIZE:" at 11733.46,5757 h60
  text "24" at 12799.71,5757 h60
  text "MIL" at 12984.46,5757 h60
  text "0.05mm (2MIL)" at 12428.46,5615.29 h60
  text "MINIMUM ANNULAR RING" at 11404.23,5611 h60
  text "EXTERNAL" at 13136.46,5611 h60
  text "PER" at 11604.23,5493 h60
  text "IPC-D-275 CLASS 2 LEVEL C" at 11824.23,5493 h60
  text "MIL, HOLES" at 13312.46,5380.71 h60
  text "+/-" at 12920,5380 h60
  text "+/-" at 13774,5380 h60
  text "REGISTRATION TOLERANCES:" at 11404.23,5375 h60
  text "METAL" at 12604,5375 h60
  text "5" at 13180.2,5375 h60
  text "3" at 14013.2,5375 h60
  text "MIL" at 14129.46,5375 h60
  text "+/-" at 13774,5262 h60
  text "HOLE SIZE TOLERANCE (UNLESS OTHERWISE SPECIFIED):" at 11404.23,5257 h60
  text "3" at 14013.2,5257 h60
  text "MIL" at 14129.46,5257 h60
  text "MATERIAL:" at 11329.46,5047.54 h60
  text "FR-4 High Tg" at 12315.9,4907.21 h60
  text "FR-408" at 11750.46,4898.64 h60
  text "OTHER" at 13238.46,4898.64 h60
  text "X" at 12161,4895 h60
  text "62 MIL (1.6mm) +/-10%" at 12070.56,4735.92 h60
  text "THICKNESS:" at 11404.23,4731.64 h60
  text "X" at 11942.4,4731.64 h60
  text "OTHER" at 13355.46,4731.64 h60
  text "TOLERANCE:" at 11404.23,4573.64 h60
  text "X" at 12243.53,4573.64 h60
  text "ANSI IPC-6012 TYPE 3 CLASS 2" at 12430.48,4573.64 h60
  text "OTHER +/-" at 12430.46,4417.64 h60
  text "BOW & TWIST:" at 11404.23,4260.64 h60
  text "X" at 12243.53,4260.64 h60
  text "ANSI IPC-6012 TYPE 3 CLASS 2" at 12430.48,4260.64 h60
  text "OTHER +/-" at 12430.46,4102.13 h60
  text "DRILLING:" at 11329.46,3963.64 h60
  text "REFERENCE:" at 11404.23,3846.64 h60
  text "X" at 12052.46,3846.64 h60
  text "AS SHOWN" at 12239.46,3846.64 h60
  text "X" at 12953.46,3846.64 h60
  text "NC_DRILL FILES" at 13090.46,3846.64 h60
  text "PTH COPPER THICKNESS:" at 11404.23,3688.64 h60
  text "X" at 12534.46,3688.64 h60
  text "20-30 um" at 12671.46,3688.64 h60
  text "OTHER" at 13388.46,3688.64 h60
  text "BOARD FINISH:" at 11329.46,3529.64 h60
  text "SILKSCREEN:" at 11484.68,3411.64 h60
  text "X" at 12433.46,3411.64 h60
  text "TOP" at 12559.46,3411.64 h60
  text "X" at 12943.46,3411.64 h60
  text "BOTTOM" at 13070.46,3411.64 h60
  text "SILKSCREEN COLOR:" at 11484.68,3244.64 h60
  text "X" at 12432.42,3244.64 h60
  text "WHITE" at 12559.46,3244.64 h60
  text "OTHER" at 13070.46,3244.64 h60
  text "X" at 12563.42,3085.44 h60
  text "GREEN" at 12690.46,3085.44 h60
  text "OTHER" at 13308.46,3085.44 h60
  text "SOLDER RESIST COLOR:" at 11484.68,3074.64 h60
  text "X" at 12563.42,2915.44 h60
  text "MATTE" at 12690.46,2915.44 h60
  text "SEMI-GLOSS" at 13308,2914.8 h60
  text "IMMERSION GOLD (ENIG)" at 12390.46,2726.92 h60
  text "ENEPIG" at 13728,2723.64 h60
  text "SURFACE FINISH:" at 11329.46,2722.64 h60
  text "X" at 12203.51,2722.64 h60
  text "IMM. TIN/SILVER OR EQUIV" at 11659,2565.64 h60
  text "OTHER" at 13090.46,2565.64 h60
  text "ARRAY/PANEL:" at 11329.46,2386.64 h60
  text "CUT AND TRIM PER M1 BOARD OUTLINE" at 12390.46,2382.35 h60
  text "N.C. ROUTE" at 12390.46,2230.64 h60
  text "X" at 13069.46,2230.64 h60
  text "V. SCORE" at 13256.46,2230.64 h60
  text "CERTIFICATION:" at 11329.46,2093.64 h60
  text "MATERIALS AND WORKMANSHIP FOR ALL PCBS" at 12054.46,2093.64 h60
  text "TO MEET OR EXCEED THE REQUIREMENTS OF:" at 12054.46,1995.64 h60
  text "X" at 11680.96,1859.13 h60
  text "ANSI IPC-A-600F CLASS ->" at 11819.96,1859.13 h60
  text "X" at 13459.02,1859.13 h60
  text "2" at 13577.96,1859.14 h60
  text "1" at 13262.96,1857.64 h60
  text "3" at 13931.96,1857.64 h60
  text "X" at 12495.02,1699.64 h60
  text "RoHS" at 12631.96,1699.64 h60
  text "OTHER" at 13276.36,1699.64 h60
  text "PER ORDER" at 13673.42,1699.64 h60
  text "ALL BOARDS MUST MEET OR EXCEED UL94-V0 REQUIREMENTS." at 11357,1534 h60
  text "PCB MUST BEAR THE UL94V-0 UL REGISTERED MATERIAL ID NUMBER" at 11357,1414 h60
  text "ADDITIONAL REQUIREMENTS:" at 11329.46,1240.64 h60
  text "MICROSECTION:" at 11404.23,1125.64 h60
  text "YES" at 12309.96,1125.64 h60
  text "REQUIRED" at 13171.46,969.49 h60
  text "BARE BOARD ELEC. TEST:" at 11404.23,966.64 h60
  text "NONE" at 12709.96,966.64 h60
  text "X" at 13044.46,966.64 h60
  text "PER ORDER" at 13763.46,966.64 h60
  text ".Layer_Name" at 577,-858.49 h60
M11 Gerber Information:
  lines w10: -292,-930.17 6308,-930.17 ; -292,-726.83 6310,-726.83 ; -292,-523.5 -292,-1133.5 3713,-1133.5 6310,-1133.5 6310,-523.5 -291.5,-523.5 -291.5,-1133.5 1284,-1133.5 ; 2173,-1133.5 2173,-523.5 ; 3440,-726.83 3440,-523.5 ; 4280,-726.83 4280,-523.5 ; 4902,-1140 4902,-937.17
  text "ALL ARTWORK VIEWED FROM TOP SIDE" at -228.5,-655.67 h60
  text "BOARD #:" at 2248,-655.67 h60
  text ".PRJ_Number" at 2793.5,-655.67 h60
  text "REV:" at 3638,-655.67 h60
  text ".PCB_Rev" at 3929.5,-655.67 h60
  text "SVN REV:" at 4476,-655.67 h60
  text ".VersionControl_RevNumber" at 4982,-655.67 h60
  text "LAYER NAME =" at -228.5,-858.49 h60
  text "TID #:" at 2248,-859 h60
  text ".TID" at 2793.5,-859 h60
  text "PLOT NAME =" at -228.5,-1064.34 h60
  text ".plot_File_Name" at 577,-1064.34 h60
  text "GENERATED    :" at 2250,-1064.34 h60
  text ".Print_Date" at 3119.5,-1064.34 h60
  text ".Print_Time" at 3848.5,-1064.34 h60
  text "TEXAS INSTRUMENTS" at 5113,-1064.34 h60
M12 Stackup:
  drawing of 191 lines, arcs and shapes, not listed
  text "Layer" at 9790.34,7830 h60
  text "Name" at 10200.26,7830 h60
  text "Material" at 11130,7830 h60
  text "Thickness" at 11989.77,7830 h60
  text "Constant" at 12639.6,7830 h60
  text "Board Layer Stack" at 13209.46,7830 h60
  text "1" at 9790.34,7710 h60
  text "Top Overlay" at 10200.26,7710 h60
  text "2" at 9790.34,7590 h60
  text "Top Solder" at 10200.26,7590 h60
  text "Solder Resist" at 11130,7590 h60
  text "0.40mil" at 11989.77,7590 h60
  text "3.5" at 12639.6,7590 h60
  text "3" at 9790.34,7470 h60
  text "Top Layer" at 10200.26,7470 h60
  text "Copper" at 11130,7470 h60
  text "1.40mil" at 11989.77,7470 h60
  text "4" at 9790.34,7350 h60
  text "Dielectric1" at 10200.26,7350 h60
  text "FR-4" at 11130,7350 h60
  text "59.20mil" at 11989.77,7350 h60
  text "4.8" at 12639.6,7350 h60
  text "5" at 9790.34,7230 h60
  text "Bottom Layer" at 10200.26,7230 h60
  text "Copper" at 11130,7230 h60
  text "1.40mil" at 11989.77,7230 h60
  text "6" at 9790.34,7110 h60
  text "Bottom Solder" at 10200.26,7110 h60
  text "Solder Resist" at 11130,7110 h60
  text "0.40mil" at 11989.77,7110 h60
  text "3.5" at 12639.6,7110 h60
  text "7" at 9790.34,6990 h60
  text "Bottom Overlay" at 10200.26,6990 h60
  text ".Layer_Name" at 577,-858.49 h60
M13 Component Bodies Top:
  text ".Layer_Name" at 577,-858.49 h60
M14 Component Bodies Bottom:
  text ".Layer_Name" at 577,-858.49 h60
M15 Courtyards Top:
  text ".Layer_Name" at 577,-858.49 h60
M16 Courtyards Bottom:
  text ".Layer_Name" at 577,-858.49 h60
Drill Drawing:
  circle w10: c5363.72,2769 r27.63
  lines w10: 5336.09,2920.95 5391.34,2920.95 5363.72,2865.7 5336.09,2920.95 ; 5336.09,2990.02 5391.34,2990.02 5391.34,3045.27 5336.09,3045.27 5336.09,2990.02 ; 5336.09,3128.15 5349.9,3128.15 5363.72,3114.34 5377.53,3128.15 5391.34,3128.15 5377.53,3141.96 5391.34,3155.78 5377.53,3155.78 5363.72,3169.59 5349.9,3155.78 5336.09,3155.78 5349.9,3141.96 5336.09,3128.15 ; 5336.09,3238.66 5363.72,3252.47 5391.34,3238.66 5377.53,3266.28 5391.34,3293.91 5363.72,3280.1 5336.09,3293.91 5349.9,3266.28 5336.09,3238.66
  lines w12: 5286,2704.08 8517.49,2704.08 ; 5286,3325.68 8517.49,3325.68 ; 5623.86,2579.76 5623.86,3450 ; 5955.86,2579.76 5955.86,3450 ; 6592.43,2579.76 6592.43,3450 ; 6851.57,2579.76 6851.57,3450 ; 7226.72,2579.76 7226.72,3450 ; 7951.05,2579.76 7951.05,3450 ; 5286,2579.76 8517.49,2579.76 8517.49,3450 5286,3450 5286,2579.76
  text "Symbol" at 5360.59,3362.98 h72
  text "Quantity" at 5661.16,3362.98 h72
  text "Finished Hole Size" at 5993.16,3362.98 h72
  text "Plated" at 6629.72,3362.98 h72
  text "Hole Type" at 6888.86,3362.98 h72
  text "Drill Layer Pair" at 7264.02,3362.98 h72
  text "Hole Tolerance" at 7988.35,3362.98 h72
  text "7" at 5661.16,3238.66 h60
  text "16.00mil (0.406mm)" at 5993.16,3238.66 h60
  text "PTH" at 6629.72,3238.66 h60
  text "Round" at 6888.86,3238.66 h60
  text "Top Layer - Bottom Layer" at 7264.02,3238.66 h60
  text "20" at 5661.16,3114.34 h60
  text "47.24mil (1.200mm)" at 5993.16,3114.34 h60
  text "PTH" at 6629.72,3114.34 h60
  text "Round" at 6888.86,3114.34 h60
  text "Top Layer - Bottom Layer" at 7264.02,3114.34 h60
  text "18" at 5661.16,2990.02 h60
  text "49.21mil (1.250mm)" at 5993.16,2990.02 h60
  text "PTH" at 6629.72,2990.02 h60
  text "Round" at 6888.86,2990.02 h60
  text "Top Layer - Bottom Layer" at 7264.02,2990.02 h60
  text "8" at 5661.16,2865.7 h60
  text "80.71mil (2.050mm)" at 5993.16,2865.7 h60
  text "PTH" at 6629.72,2865.7 h60
  text "Round" at 6888.86,2865.7 h60
  text "Top Layer - Bottom Layer" at 7264.02,2865.7 h60
  text "4" at 5661.16,2741.38 h60
  text "125.98mil (3.200mm)" at 5993.16,2741.38 h60
  text "PTH" at 6629.72,2741.38 h60
  text "Round" at 6888.86,2741.38 h60
  text "Top Layer - Bottom Layer" at 7264.02,2741.38 h60
  text "57 Total" at 5661.16,2617.06 h60
  text ".Layer_Name" at 577,-858.49 h60
M17 Embedded Cavity:
  text ".Layer_Name" at 577,-858.49 h60
M18 Embedded Assembly:
  text ".Layer_Name" at 577,-858.49 h60
M19 Embedded Keepout:
  text ".Layer_Name" at 577,-858.49 h60

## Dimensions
0,-400 to 1000,-400 on M2 Board Dimensions
0,0 to 0,3450 on M2 Board Dimensions
0,0 to 4220,0 on M2 Board Dimensions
